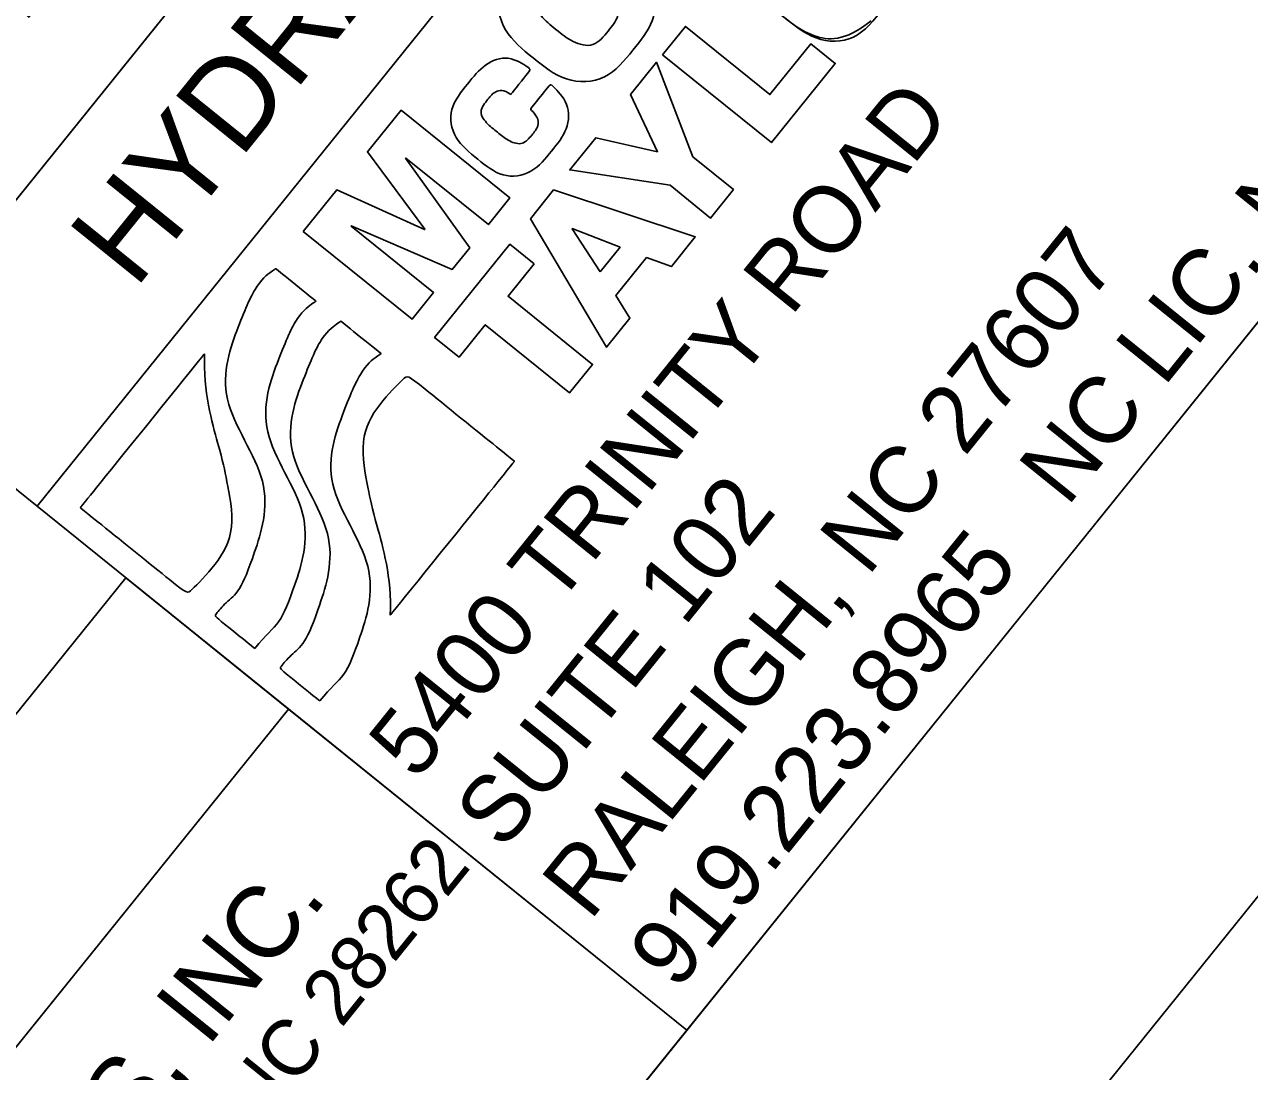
# Model space of a CAD drawing. Extents: x 1487832 to 1490056, y 498345 to 500343.
# Drawn here: x 1489651.2 to 1489727.7, y 499575.2 to 499640.6 of the extents above; entities that cross this region are included whole.
import ezdxf

# ---------------------------------------------------------------- set-up
doc = ezdxf.new("R2010")
doc.units = 0
for name, color, linetype in [('Prop Grid Mask', 7, 'Continuous'), ('Prop Horizontal Alignment Curve and Spiral Data', 7, 'Continuous'), ('Sheet Block Title CELL', 7, 'Continuous'), ('Sheet Clip Boundary CELL', 7, 'Continuous'), ('Sheet Plan CELL', 7, 'Continuous'), ('Sheet Plot Border Outside CELL', 7, 'Continuous')]:
    doc.layers.add(name, color=color, linetype=linetype)

msp = doc.modelspace()

# ---------------------------------------------------------------- linework, layer by layer
at = {"layer": 'Prop Grid Mask'}
for p, q in [((1489691.057, 499638.711), (1489692.484, 499640.482)), ((1489692.484, 499640.482), (1489697.757, 499636.229)), ((1489697.757, 499636.229), (1489700.313, 499639.399)), ((1489700.313, 499639.399), (1489701.836, 499638.171)), ((1489689.06, 499636.236), (1489690.68, 499638.244)), ((1489690.68, 499638.244), (1489692.948, 499632.331)), ((1489697.852, 499633.231), (1489691.057, 499638.711)), ((1489701.836, 499638.171), (1489697.852, 499633.231)), ((1489690.731, 499632.658), (1489689.06, 499636.236)), ((1489672.625, 499632.643), (1489674.728, 499635.251)), ((1489674.728, 499635.251), (1489681.524, 499629.771)), ((1489685.261, 499631.524), (1489686.88, 499633.532)), ((1489686.88, 499633.532), (1489690.731, 499632.658)), ((1489676.211, 499627.819), (1489672.625, 499632.643)), ((1489675.022, 499632.265), (1489675.007, 499632.246)), ((1489675.007, 499632.246), (1489679.014, 499626.659)), ((1489680.181, 499628.105), (1489675.022, 499632.265)), ((1489692.948, 499632.331), (1489695.48, 499630.289)), ((1489691.52, 499630.56), (1489685.261, 499631.524)), ((1489694.052, 499628.519), (1489691.52, 499630.56)), ((1489668.618, 499627.675), (1489670.722, 499630.283)), ((1489670.722, 499630.283), (1489676.196, 499627.8)), ((1489681.524, 499629.771), (1489680.181, 499628.105)), ((1489682.802, 499628.475), (1489684.252, 499630.274)), ((1489684.252, 499630.274), (1489693.097, 499627.335)), ((1489695.48, 499630.289), (1489694.052, 499628.519)), ((1489687.548, 499620.454), (1489682.802, 499628.475)), ((1489675.414, 499622.194), (1489668.618, 499627.675)), ((1489671.614, 499628.039), (1489671.599, 499628.02)), ((1489671.599, 499628.02), (1489676.757, 499623.86)), ((1489677.924, 499625.307), (1489671.614, 499628.039)), ((1489676.196, 499627.8), (1489676.211, 499627.819)), ((1489685.415, 499627.859), (1489685.4, 499627.841)), ((1489685.4, 499627.841), (1489687.158, 499625.151)), ((1489688.401, 499626.692), (1489685.415, 499627.859)), ((1489676.821, 499621.059), (1489681.519, 499626.884)), ((1489681.519, 499626.884), (1489683.042, 499625.656)), ((1489687.158, 499625.151), (1489688.401, 499626.692)), ((1489693.097, 499627.335), (1489691.608, 499625.488)), ((1489679.014, 499626.659), (1489677.924, 499625.307)), ((1489690.053, 499626.052), (1489688.141, 499623.682)), ((1489691.608, 499625.488), (1489690.053, 499626.052)), ((1489683.042, 499625.656), (1489681.407, 499623.629)), ((1489676.757, 499623.86), (1489675.414, 499622.194)), ((1489681.407, 499623.629), (1489686.68, 499619.377)), ((1489688.141, 499623.682), (1489689.014, 499622.271)), ((1489689.014, 499622.271), (1489687.548, 499620.454)), ((1489679.979, 499621.859), (1489678.344, 499619.831)), ((1489685.252, 499617.607), (1489679.979, 499621.859)), ((1489678.344, 499619.831), (1489676.821, 499621.059)), ((1489686.68, 499619.377), (1489685.252, 499617.607))]:
    msp.add_line(p, q, dxfattribs=at)
for points in [[(1489502.46, 499445.87), (1489705.455, 499697.585), (1489601.093, 499781.747), (1489398.098, 499530.033)], [(1489651.998, 499610.518), (1489715.609, 499689.396), (1489705.455, 499697.585), (1489641.844, 499618.707)], [(1489651.998, 499610.518), (1489715.609, 499689.396), (1489756.18, 499656.677), (1489692.569, 499577.8)], [(1489528.312, 499425.022), (1489667.696, 499597.859), (1489657.541, 499606.048), (1489518.158, 499433.211)], [(1489528.311, 499425.024), (1489667.696, 499597.859), (1489692.569, 499577.8), (1489553.184, 499404.964)]]:
    msp.add_lwpolyline(points, close=True, dxfattribs=at)
for points in [[(1489691.057, 499638.711), (1489692.484, 499640.482), (1489697.757, 499636.229), (1489700.313, 499639.399), (1489701.836, 499638.171), (1489697.852, 499633.231), (1489691.057, 499638.711)], [(1489692.948, 499632.331), (1489695.48, 499630.289), (1489694.052, 499628.519), (1489691.52, 499630.56), (1489685.261, 499631.524), (1489686.88, 499633.532), (1489690.731, 499632.658), (1489689.06, 499636.236), (1489690.68, 499638.244), (1489692.948, 499632.331)], [(1489668.618, 499627.675), (1489670.722, 499630.283), (1489676.196, 499627.8), (1489676.211, 499627.819), (1489672.625, 499632.643), (1489674.728, 499635.251), (1489681.524, 499629.771), (1489680.181, 499628.105), (1489675.022, 499632.265), (1489675.007, 499632.246), (1489679.014, 499626.659), (1489677.924, 499625.307), (1489671.614, 499628.039), (1489671.599, 499628.02), (1489676.757, 499623.86), (1489675.414, 499622.194), (1489668.618, 499627.675)], [(1489682.802, 499628.475), (1489684.252, 499630.274), (1489693.097, 499627.335), (1489691.608, 499625.488), (1489690.053, 499626.052), (1489688.141, 499623.682), (1489689.014, 499622.271), (1489687.548, 499620.454), (1489682.802, 499628.475)], [(1489687.158, 499625.151), (1489688.401, 499626.692), (1489685.415, 499627.859), (1489685.4, 499627.841), (1489687.158, 499625.151)], [(1489683.042, 499625.656), (1489681.407, 499623.629), (1489686.68, 499619.377), (1489685.252, 499617.607), (1489679.979, 499621.859), (1489678.344, 499619.831), (1489676.821, 499621.059), (1489681.519, 499626.884), (1489683.042, 499625.656)]]:
    msp.add_lwpolyline(points, dxfattribs=at)
for points in [[(1489697.748, 499647.301), (1489699.475, 499649.443), (1489702.021, 499649.385), (1489703.991, 499647.797), (1489705.961, 499646.207), (1489706.557, 499643.732), (1489704.83, 499641.591), (1489703.103, 499639.449), (1489700.558, 499639.507), (1489698.587, 499641.096), (1489696.617, 499642.685), (1489696.021, 499645.16), (1489697.748, 499647.301)], [(1489685.807, 499644.021), (1489685.045, 499644.479), (1489684.253, 499644.237), (1489683.654, 499643.495), (1489682.733, 499642.353), (1489683.389, 499641.102), (1489684.398, 499640.288), (1489685.407, 499639.475), (1489686.769, 499639.099), (1489687.69, 499640.241), (1489688.358, 499641.069), (1489688.266, 499641.928), (1489687.539, 499642.624), (1489687.539, 499642.624), (1489688.967, 499644.395), (1489688.967, 499644.395), (1489690.641, 499642.887), (1489690.632, 499640.774), (1489689.243, 499639.051), (1489687.585, 499636.995), (1489684.941, 499636.929), (1489682.97, 499638.518), (1489681, 499640.106), (1489680.504, 499642.705), (1489682.162, 499644.761), (1489683.344, 499646.227), (1489685.559, 499647.064), (1489687.234, 499645.792), (1489687.234, 499645.792), (1489685.807, 499644.021), (1489685.807, 499644.021)], [(1489685.807, 499644.021), (1489685.045, 499644.479), (1489684.253, 499644.237), (1489683.654, 499643.495), (1489682.733, 499642.353), (1489683.389, 499641.102), (1489684.398, 499640.288), (1489685.407, 499639.475), (1489686.769, 499639.099), (1489687.69, 499640.241), (1489688.358, 499641.069), (1489688.266, 499641.928), (1489687.539, 499642.624), (1489687.539, 499642.624), (1489688.967, 499644.395), (1489688.967, 499644.395), (1489690.641, 499642.887), (1489690.632, 499640.774), (1489689.243, 499639.051), (1489687.585, 499636.995), (1489684.941, 499636.929), (1489682.97, 499638.518), (1489681, 499640.106), (1489680.504, 499642.705), (1489682.162, 499644.761), (1489683.344, 499646.227), (1489685.559, 499647.064), (1489687.234, 499645.792), (1489687.234, 499645.792), (1489685.807, 499644.021), (1489685.807, 499644.021)], [(1489704.078, 499640.833), (1489702.417, 499639.494), (1489700.288, 499639.724), (1489698.587, 499641.096), (1489696.617, 499642.685), (1489696.021, 499645.16), (1489697.748, 499647.301)], [(1489681.569, 499636.235), (1489681.142, 499636.562), (1489680.548, 499636.429), (1489680.218, 499636.02), (1489679.489, 499635.116), (1489680.144, 499634.351), (1489680.83, 499633.799), (1489681.467, 499633.285), (1489682.347, 499633.031), (1489682.9, 499633.716), (1489683.352, 499634.277), (1489683.259, 499634.824), (1489682.797, 499635.323), (1489682.797, 499635.323), (1489684.063, 499636.893), (1489684.063, 499636.893), (1489685.271, 499635.683), (1489685.203, 499634.042), (1489684.144, 499632.728), (1489682.947, 499631.243), (1489681.038, 499630.96), (1489679.525, 499632.181), (1489677.954, 499633.447), (1489677.637, 499635.352), (1489678.919, 499636.942), (1489679.909, 499638.169), (1489681.439, 499638.742), (1489682.835, 499637.805), (1489682.835, 499637.805), (1489681.569, 499636.235), (1489681.569, 499636.235)], [(1489681.569, 499636.235), (1489681.142, 499636.562), (1489680.548, 499636.429), (1489680.218, 499636.02), (1489679.489, 499635.116), (1489680.144, 499634.351), (1489680.83, 499633.799), (1489681.467, 499633.285), (1489682.347, 499633.031), (1489682.9, 499633.716), (1489683.352, 499634.277), (1489683.259, 499634.824), (1489682.797, 499635.323), (1489682.797, 499635.323), (1489684.063, 499636.893), (1489684.063, 499636.893), (1489685.271, 499635.683), (1489685.203, 499634.042), (1489684.144, 499632.728), (1489682.947, 499631.243), (1489681.038, 499630.96), (1489679.525, 499632.181), (1489677.954, 499633.447), (1489677.637, 499635.352), (1489678.919, 499636.942), (1489679.909, 499638.169), (1489681.439, 499638.742), (1489682.835, 499637.805), (1489682.835, 499637.805), (1489681.569, 499636.235), (1489681.569, 499636.235)], [(1489665.587, 499601.644), (1489666.291, 499602.518), (1489667.157, 499603.116), (1489667.974, 499605.19), (1489669.515, 499609.983), (1489665.417, 499615.248), (1489667.189, 499620.064), (1489668.231, 499622.515), (1489669.414, 499623.329), (1489669.414, 499623.329), (1489669.414, 499623.329), (1489666.899, 499625.357), (1489666.899, 499625.357), (1489666.899, 499625.357), (1489665.717, 499624.542), (1489664.675, 499622.092), (1489662.902, 499617.275), (1489667.001, 499612.01), (1489665.46, 499607.218), (1489664.643, 499605.144), (1489663.777, 499604.546), (1489663.072, 499603.672), (1489663.072, 499603.672), (1489665.587, 499601.644), (1489665.587, 499601.644)], [(1489665.587, 499601.644), (1489666.291, 499602.518), (1489667.157, 499603.116), (1489667.974, 499605.19), (1489669.515, 499609.983), (1489665.417, 499615.248), (1489667.189, 499620.064), (1489668.231, 499622.515), (1489669.414, 499623.329), (1489669.414, 499623.329), (1489669.414, 499623.329), (1489666.899, 499625.357), (1489666.899, 499625.357), (1489666.899, 499625.357), (1489665.717, 499624.542), (1489664.675, 499622.092), (1489662.902, 499617.275), (1489667.001, 499612.01), (1489665.46, 499607.218), (1489664.643, 499605.144), (1489663.777, 499604.546), (1489663.072, 499603.672), (1489663.072, 499603.672), (1489665.587, 499601.644), (1489665.587, 499601.644)], [(1489669.651, 499598.366), (1489670.356, 499599.24), (1489671.221, 499599.838), (1489672.038, 499601.913), (1489673.58, 499606.705), (1489669.481, 499611.97), (1489671.254, 499616.786), (1489672.295, 499619.237), (1489673.478, 499620.052), (1489673.478, 499620.052), (1489673.478, 499620.052), (1489670.964, 499622.079), (1489670.964, 499622.079), (1489670.964, 499622.079), (1489669.781, 499621.265), (1489668.739, 499618.814), (1489666.967, 499613.998), (1489671.066, 499608.732), (1489669.524, 499603.94), (1489668.707, 499601.866), (1489667.841, 499601.268), (1489667.137, 499600.394), (1489667.137, 499600.394), (1489669.651, 499598.366), (1489669.651, 499598.366)], [(1489669.651, 499598.366), (1489670.356, 499599.24), (1489671.221, 499599.838), (1489672.038, 499601.913), (1489673.58, 499606.705), (1489669.481, 499611.97), (1489671.254, 499616.786), (1489672.295, 499619.237), (1489673.478, 499620.052), (1489673.478, 499620.052), (1489673.478, 499620.052), (1489670.964, 499622.079), (1489670.964, 499622.079), (1489670.964, 499622.079), (1489669.781, 499621.265), (1489668.739, 499618.814), (1489666.967, 499613.998), (1489671.066, 499608.732), (1489669.524, 499603.94), (1489668.707, 499601.866), (1489667.841, 499601.268), (1489667.137, 499600.394), (1489667.137, 499600.394), (1489669.651, 499598.366), (1489669.651, 499598.366)], [(1489662.451, 499620.048), (1489662.348, 499617.684), (1489663.517, 499613.738), (1489663.784, 499612.385), (1489664.446, 499609.04), (1489663.211, 499606.833), (1489661.375, 499605.041), (1489661.375, 499605.041), (1489654.693, 499610.429), (1489654.693, 499610.429), (1489654.693, 499610.429), (1489662.451, 499620.048), (1489662.451, 499620.048)], [(1489662.451, 499620.048), (1489662.348, 499617.684), (1489663.517, 499613.738), (1489663.784, 499612.385), (1489664.446, 499609.04), (1489663.211, 499606.833), (1489661.375, 499605.041), (1489661.375, 499605.041), (1489654.693, 499610.429), (1489654.693, 499610.429), (1489654.693, 499610.429), (1489662.451, 499620.048), (1489662.451, 499620.048)], [(1489674.049, 499603.715), (1489674.152, 499606.079), (1489672.983, 499610.025), (1489672.716, 499611.378), (1489672.054, 499614.723), (1489673.289, 499616.93), (1489675.125, 499618.722), (1489675.125, 499618.722), (1489681.807, 499613.334), (1489681.807, 499613.334), (1489681.807, 499613.334), (1489674.049, 499603.715), (1489674.049, 499603.715)], [(1489674.049, 499603.715), (1489674.152, 499606.079), (1489672.983, 499610.025), (1489672.716, 499611.378), (1489672.054, 499614.723), (1489673.289, 499616.93), (1489675.125, 499618.722), (1489675.125, 499618.722), (1489681.807, 499613.334), (1489681.807, 499613.334), (1489681.807, 499613.334), (1489674.049, 499603.715), (1489674.049, 499603.715)]]:
    msp.add_open_spline(points, degree=3, dxfattribs=at)
at = {"layer": 'Sheet Block Title CELL'}
msp.add_lwpolyline([(1489528.311, 499425.024), (1489667.696, 499597.859), (1489692.569, 499577.8), (1489553.184, 499404.964)], close=True, dxfattribs=at)
at = {"layer": 'Sheet Clip Boundary CELL'}
msp.add_lwpolyline([(1488948.365, 500051.157), (1488813.253, 500160.101), (1488087.836, 499260.526), (1488879.089, 498569.078), (1489756.18, 499656.677), (1489073.938, 500206.869)], close=True, dxfattribs=at)
at = {"layer": 'Sheet Plan CELL'}
for points in [[(1488938.86, 500315.835), (1487997.211, 499148.184), (1488814.546, 498489.046), (1489756.18, 499656.677)], [(1488814.546, 498489.046), (1487997.215, 499148.149), (1488813.253, 500160.101), (1488930.072, 500065.909), (1489055.655, 500221.614), (1489756.18, 499656.677)]]:
    msp.add_lwpolyline(points, close=True, dxfattribs=at)
at = {"layer": 'Sheet Plot Border Outside CELL'}
msp.add_lwpolyline([(1488727.558, 498345.317), (1489784.376, 499655.778), (1488932.012, 500343.165), (1487875.194, 499032.704)], close=True, dxfattribs=at)

# ---------------------------------------------------------------- texts
at = {"layer": 'Prop Grid Mask'}
for s, height, p in [('919.223.8965   NC LIC. NO. F-1285', 4.17727, (1489691.945, 499580.199)), ('5400 TRINITY ROAD', 4.17727, (1489675.687, 499593.31)), ('RALEIGH, NC 27607', 4.17727, (1489686.526, 499584.57)), ('SUITE 102', 4.1773, (1489681.107, 499588.94))]:
    msp.add_text(s, height=height, rotation=51.11565, dxfattribs=at).set_placement(p)
at = {"layer": 'Prop Horizontal Alignment Curve and Spiral Data'}
for s, p in [('PLAN SET BEFORE START OF CONSTRUCTION. ANY DISCREPANCIES SHALL', (1489488.399, 499492.532)), ('ELEVATIONS POST NEW CROSSING  PANEL INSTALLATION.  CONTRACTOR', (1489501.534, 499481.939)), ('BE BROUGHT TO THE ATTENTION OF CSX.  FIELD VERIFY TOP OF RAIL', (1489494.966, 499487.235)), ('HYDRAULIC DESIGN', (1489658.114, 499624.012)), ('TO FIELD ADJUST PROFILE AT DIRECTION OF ENGINEER AT TIE-INS TO', (1489508.102, 499476.642)), ('THE NEW CROSSING SURFACE PANEL AS THE ELEVATION MAY CHANGE.', (1489514.67, 499471.346))]:
    msp.add_text(s, height=5.625, rotation=51.11565, dxfattribs=at).set_placement(p)
at = {"layer": 'Sheet Block Title CELL'}
for s, height, p in [('10735 DAVID TAYLOR DRIVE, SUITE 310   CHARLOTTE, NC 28262', 3.5, (1489587.718, 499474.631)), ('A. MORTON THOMAS AND ASSOCIATES, INC.', 4.5, (1489587.698, 499483.765))]:
    msp.add_text(s, height=height, rotation=51.11516, dxfattribs=at).set_placement(p)

doc.saveas('drawing.dxf')
